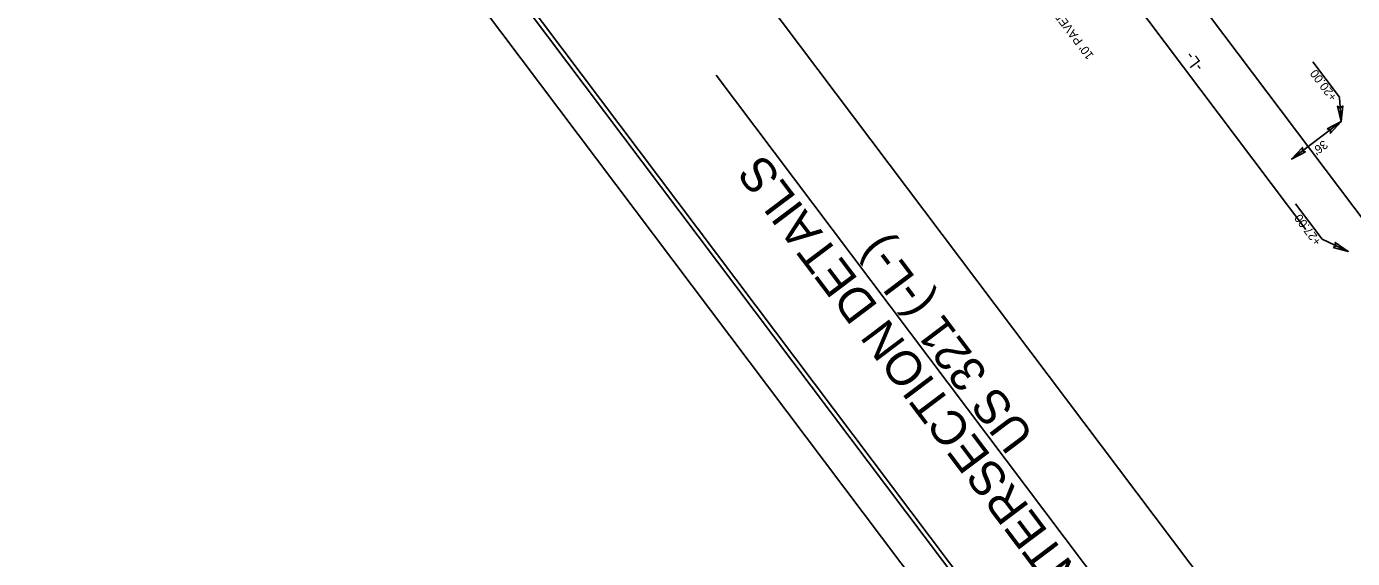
# Model space of a CAD drawing. Extents: x 1262917 to 1264804, y 775326 to 777329.
# Drawn here: x 1262917 to 1263684, y 776000 to 776309 of the extents above; entities that cross this region are included whole.
import ezdxf

# ---------------------------------------------------------------- set-up
doc = ezdxf.new("R2010")
doc.units = 0
for name, color, linetype in [('Prop Dimension', 7, 'Continuous'), ('Prop Dimension Text', 7, 'Continuous'), ('Prop Horizontal Alignment Curve and Spiral Data', 7, 'Continuous'), ('Prop Horizontal Alignment Direction Label', 7, 'Continuous'), ('Prop Lane Lines', 7, 'Continuous'), ('Prop Terminator CELL', 7, 'Continuous'), ('Scratch_Level_1', 7, 'Continuous'), ('Sheet Plot Border Inside CELL', 7, 'Continuous'), ('Sheet Plot Border Outside CELL', 7, 'Continuous'), ('Sheet Typical CELL', 7, 'Continuous')]:
    doc.layers.add(name, color=color, linetype=linetype)

msp = doc.modelspace()

# ---------------------------------------------------------------- linework, layer by layer
at = {"layer": 'Prop Dimension Text'}
for p, q in [((1263676.92, 776267.59), (1263661.47, 776288.1)), ((1263676.96, 776267.54), (1263677.97, 776253.49)), ((1263677.97, 776253.49), (1263649.21, 776231.83)), ((1263651.44, 776205.96), (1263666.94, 776185.37)), ((1263666.94, 776185.37), (1263682, 776178.33))]:
    msp.add_line(p, q, dxfattribs=at)
at = {"layer": 'Prop Horizontal Alignment Curve and Spiral Data'}
msp.add_line((1263551.12, 775968.32), (1263315.97, 776280.51), dxfattribs=at)
at = {"layer": 'Prop Lane Lines'}
for p, q in [((1263657.37, 776191.08), (1263449.1, 776467.59)), ((1263797.93, 776054.33), (1263564.99, 776363.6))]:
    msp.add_line(p, q, dxfattribs=at)
at = {"layer": 'Prop Terminator CELL'}
for points in [[(1263678.87, 776262.58), (1263677.97, 776253.49), (1263675.72, 776262.4), (1263677.4, 776261.37)], [(1263669.85, 776249.31), (1263677.97, 776253.49), (1263671.7, 776246.77), (1263671.66, 776248.74)], [(1263657.34, 776236.01), (1263649.21, 776231.83), (1263655.48, 776238.55), (1263655.52, 776236.58)], [(1263673.18, 776180.69), (1263682, 776178.33), (1263674.45, 776183.57), (1263674.83, 776181.64)]]:
    msp.add_lwpolyline(points, close=True, dxfattribs=at)
at = {"layer": 'Scratch_Level_1'}
msp.add_lwpolyline([(1263815.66, 775698.62), (1263313.44, 776365.4), (1263569.52, 776558.29), (1264071.75, 775891.5)], close=True, dxfattribs=at)
at = {"layer": 'Sheet Plot Border Inside CELL'}
msp.add_lwpolyline([(1264780.22, 775982.89), (1263777.88, 777313.61), (1262935.19, 776678.9), (1263937.52, 775348.16)], close=True, dxfattribs=at)
at = {"layer": 'Sheet Plot Border Outside CELL'}
msp.add_lwpolyline([(1262916.5, 776670.46), (1263929.36, 775325.74), (1264804.01, 775984.53), (1263791.15, 777329.26)], close=True, dxfattribs=at)
at = {"layer": 'Sheet Typical CELL'}
msp.add_line((1263847.15, 775472.26), (1262944.69, 776670.41), dxfattribs=at)
msp.add_lwpolyline([(1263313.44, 776365.4), (1263815.66, 775698.62), (1264110.72, 775920.86), (1263608.5, 776587.64)], close=True, dxfattribs=at)

# ---------------------------------------------------------------- texts
at = {"layer": 'Prop Dimension'}
for s, p in [("10' PAVED SHOULDER", (1263534.88, 776291.83)), ('+20.00', (1263675.89, 776267.77)), ('+27.00', (1263666.77, 776184.02))]:
    msp.add_text(s, height=5, rotation=126.98741, dxfattribs=at).set_placement(p)
at = {"layer": 'Prop Dimension Text'}
msp.add_text("36'", height=5, rotation=217.25837, dxfattribs=at).set_placement((1263667.79, 776243.04))
at = {"layer": 'Prop Horizontal Alignment Curve and Spiral Data'}
for s, p in [('INTERSECTION DETAILS', (1263534.5, 775981.55)), ('US 321 (-L-)', (1263500.68, 776071.58))]:
    msp.add_text(s, height=20, rotation=126.98742, dxfattribs=at).set_placement(p)
at = {"layer": 'Prop Horizontal Alignment Direction Label'}
msp.add_text('-L-', height=7, rotation=126.98518, dxfattribs=at).set_placement((1263598.64, 776285.54))

doc.saveas('drawing.dxf')
